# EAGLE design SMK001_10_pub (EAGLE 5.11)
AUTHOR: Nigel Batten; DATE: 16 Apr 2011; PRODUCT: SweeperMeter; RANGE: Other; VERSION: 1.0
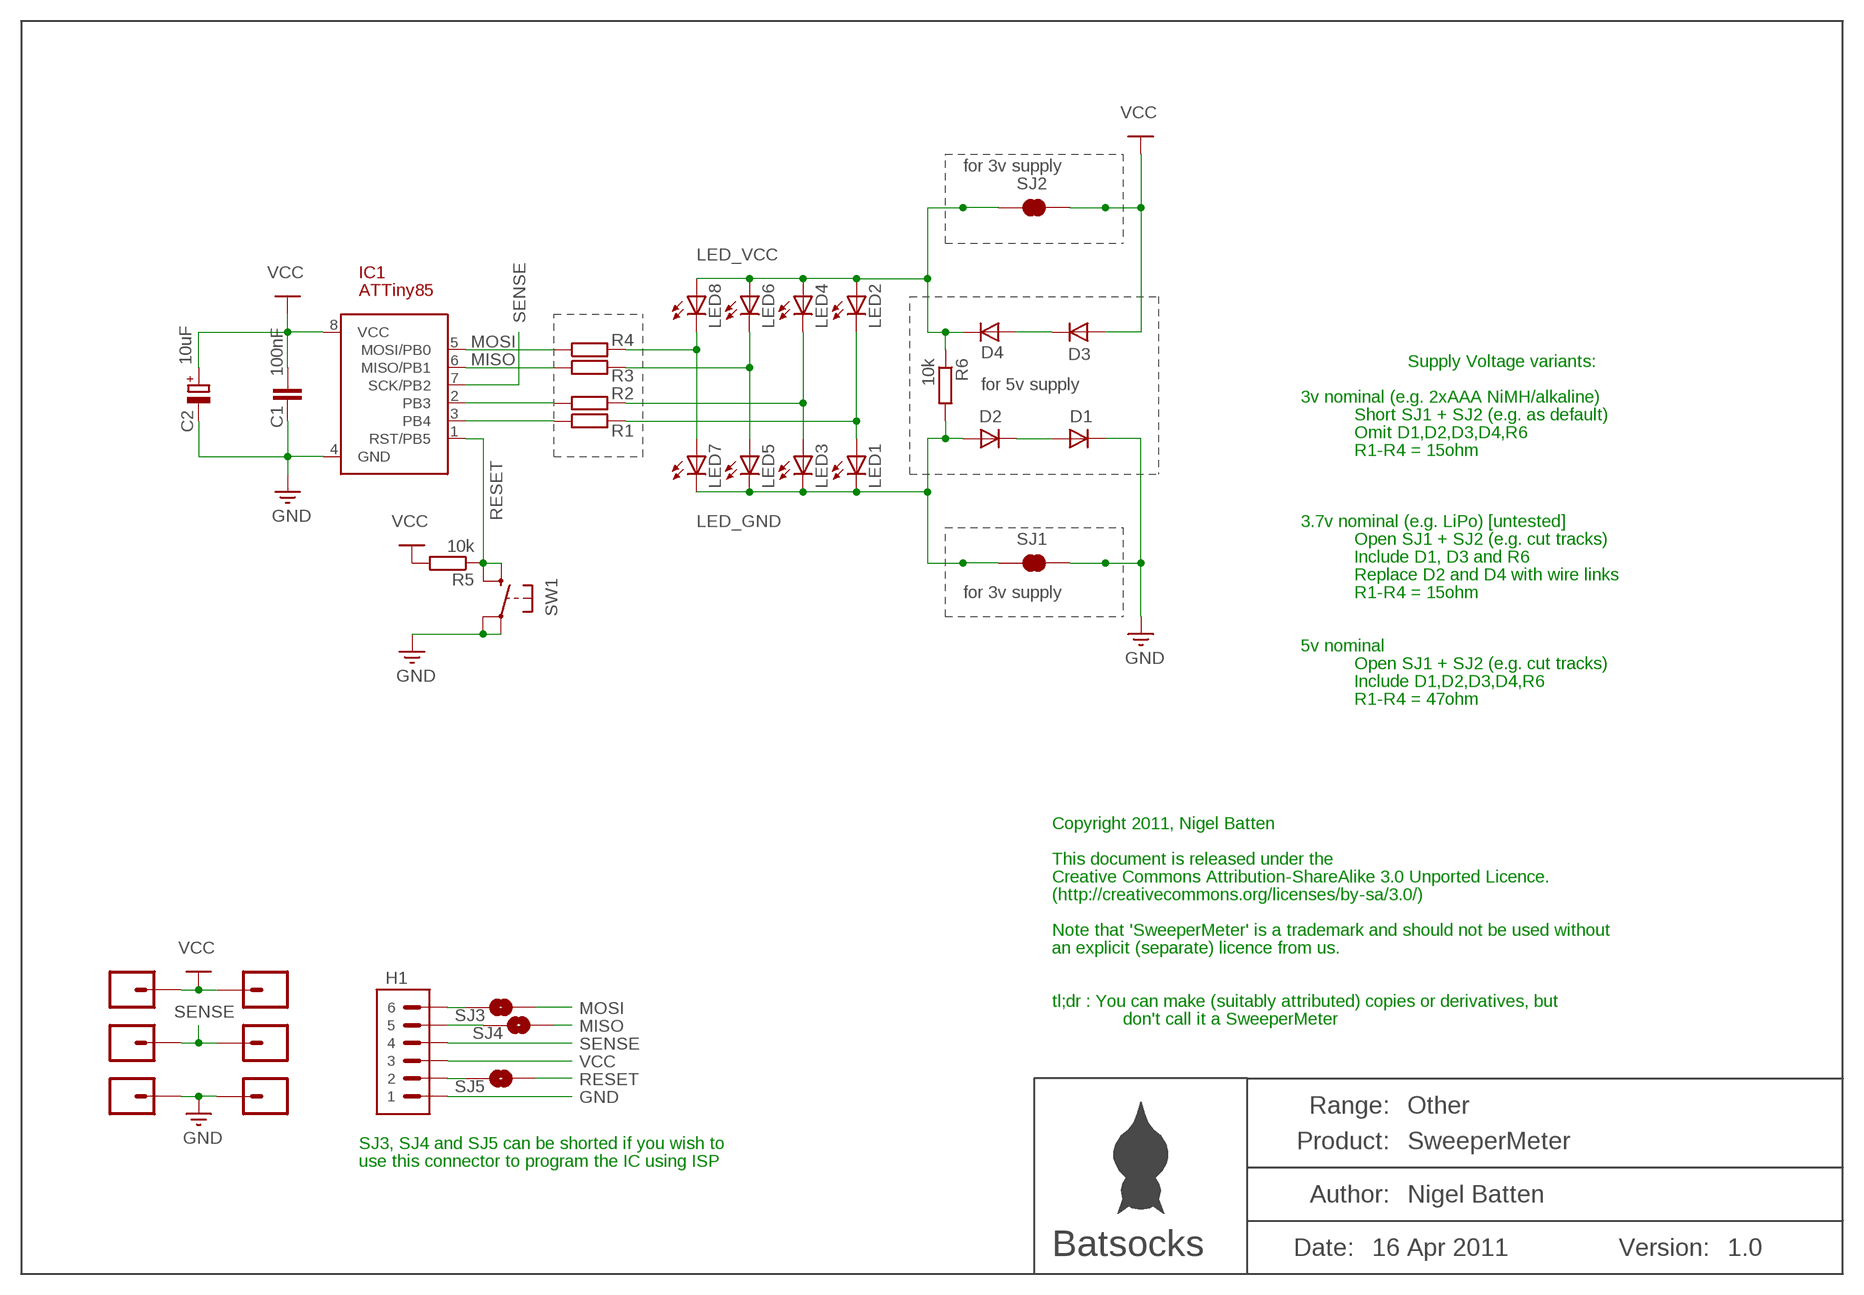
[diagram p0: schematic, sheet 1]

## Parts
C1  100nF  C_EUC050_025X075  [C050_025X075]
C2  10uF  CPOL_EUE15-4  [E15-4]
D1  DIODEDO35_7_OPT  [DO35_7_OPT]
D2  DIODEDO35_7_OPT  [DO35_7_OPT]
D3  DIODEDO35_7_OPT  [DO35_7_OPT]
D4  DIODEDO35_7_OPT  [DO35_7_OPT]
H1  HEADER_6STD  [1X06]
H10  M01FLYING_LEAD  [FLYING_LEAD_PAD]
H11  M01FLYING_LEAD  [FLYING_LEAD_PAD]
H12  M01FLYING_LEAD  [FLYING_LEAD_PAD]
H13  M01FLYING_LEAD  [FLYING_LEAD_PAD]
H14  M01FLYING_LEAD  [FLYING_LEAD_PAD]
H15  M01FLYING_LEAD  [FLYING_LEAD_PAD]
IC1  ATTiny85  ATTINY13V-10PU  [DIL08]
LED1  LED3MM  [LED3MM]
LED2  LED3MM  [LED3MM]
LED3  LED3MM  [LED3MM]
LED4  LED3MM  [LED3MM]
LED5  LED3MM  [LED3MM]
LED6  LED3MM  [LED3MM]
LED7  LED3MM  [LED3MM]
LED8  LED3MM  [LED3MM]
R1  47R  RESISTOR0207/7.5  [R0207/7.5]
R2  47R  RESISTOR0207/7.5  [R0207/7.5]
R3  47R  RESISTOR0207/7.5  [R0207/7.5]
R4  47R  RESISTOR0207/7.5  [R0207/7.5]
R5  10k  RESISTOR0204/5  [R0204/5]
R6  10k  RESISTOR0204/5_OPT  [R0204/5_OPT]
SJ1  SOLDERJUMPER_NC  [SJ_NC]
SJ2  SOLDERJUMPER_NC  [SJ_NC]
SJ3  SOLDERJUMPER_NO  [SJ_NO]
SJ4  SOLDERJUMPER_NO  [SJ_NO]
SJ5  SOLDERJUMPER_NO  [SJ_NO]
SW1  PUSHBUTTON_PTM_4ROUNDPADS  [B3F-10XX-ROUNDPADS]

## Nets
GND [power]: C1.2 C2.- D1.C H1.P$1 H11.P$1 H14.P$1 IC1.4(GND) SJ1.2 SW1.1(P) SW1.2(P1)
LED_GND [LED power]: D2.A LED1.K(C) LED3.K(C) LED5.K(C) LED7.K(C) R6.2 SJ1.1
LED_VCC [LED power]: D4.C LED2.A LED4.A LED6.A LED8.A R6.1 SJ2.1
MISO: IC1.6(MISO/PB1) R3.1 SJ4.1
MOSI: IC1.5(MOSI/PB0) R4.1 SJ3.1
N$1: H1.P$5 SJ4.2
N$3 [LED power]: LED5.A LED6.K(C) R3.2
N$4 [LED power]: LED3.A LED4.K(C) R2.2
N$5 [LED power]: LED1.A LED2.K(C) R1.2
N$6: IC1.3(PB4) R1.1
N$7: D3.C D4.A
N$8: D1.A D2.C
N$9: IC1.2(PB3) R2.1
N$11 [LED power]: LED7.A LED8.K(C) R4.2
N$14: H1.P$2 SJ5.2
N$17: H1.P$6 SJ3.2
RESET: IC1.1(RST/PB5) R5.1 SJ5.1 SW1.3(S) SW1.4(S1)
SENSE: H1.P$4 H12.P$1 H15.P$1 IC1.7(SCK/PB2)
VCC [power]: C1.1 C2.+ D3.A H1.P$3 H10.P$1 H13.P$1 IC1.8(VCC) R5.2 SJ2.2

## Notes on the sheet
- for 3v supply
- Supply Voltage variants:
- for 5v supply
- 3v nominal (e.g. 2xAAA NiMH/alkaline)
- Short SJ1 + SJ2 (e.g. as default)
- Omit D1,D2,D3,D4,R6
- R1-R4 = 15ohm
- 3.7v nominal (e.g. LiPo) [untested]
- Open SJ1 + SJ2 (e.g. cut tracks)
- Include D1, D3 and R6
- Replace D2 and D4 with wire links
- for 3v supply | R1-R4 = 15ohm
- 5v nominal
- Open SJ1 + SJ2 (e.g. cut tracks)
- Include D1,D2,D3,D4,R6
- R1-R4 = 47ohm
- Copyright 2011, Nigel Batten
- This document is released under the
- Creative Commons Attribution-ShareAlike 3.0 Unported Licence.
- (http://creativecommons.org/licenses/by-sa/3.0/)
- Note that 'SweeperMeter' is a trademark and should not be used without
- an explicit (separate) licence from us.
- H1
- tl;dr : You can make (suitably attributed) copies or derivatives, but
- don't call it a SweeperMeter
- SJ3, SJ4 and SJ5 can be shorted if you wish to
- use this connector to program the IC using ISP

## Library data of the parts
C1 = Batten:C_EU
C2 = Batten:CPOL_EU
D1-D4 = Batten:DIODE
H1 = Batten:HEADER_6
H10-H15 = Batten:M01: Header 1
IC1 = Batten:ATTINY13V-10*
LED1-LED8 = Batten:LED: LED
R1-R6 = Batten:RESISTOR
SJ1 SJ2 = Batten:SOLDERJUMPER_NC: Solder Jumper
SJ3-SJ5 = Batten:SOLDERJUMPER_NO: Solder Jumper
SW1 = Batten:PUSHBUTTON_PTM_4: OMRON B3S

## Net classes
0 default: width 0.305 mm, clearance 0.254 mm
1 power: width 0.508 mm, clearance 0.305 mm
2 LED power: width 0.508 mm, clearance 0.305 mm
3 signal: width 0.305 mm, clearance 0.254 mm

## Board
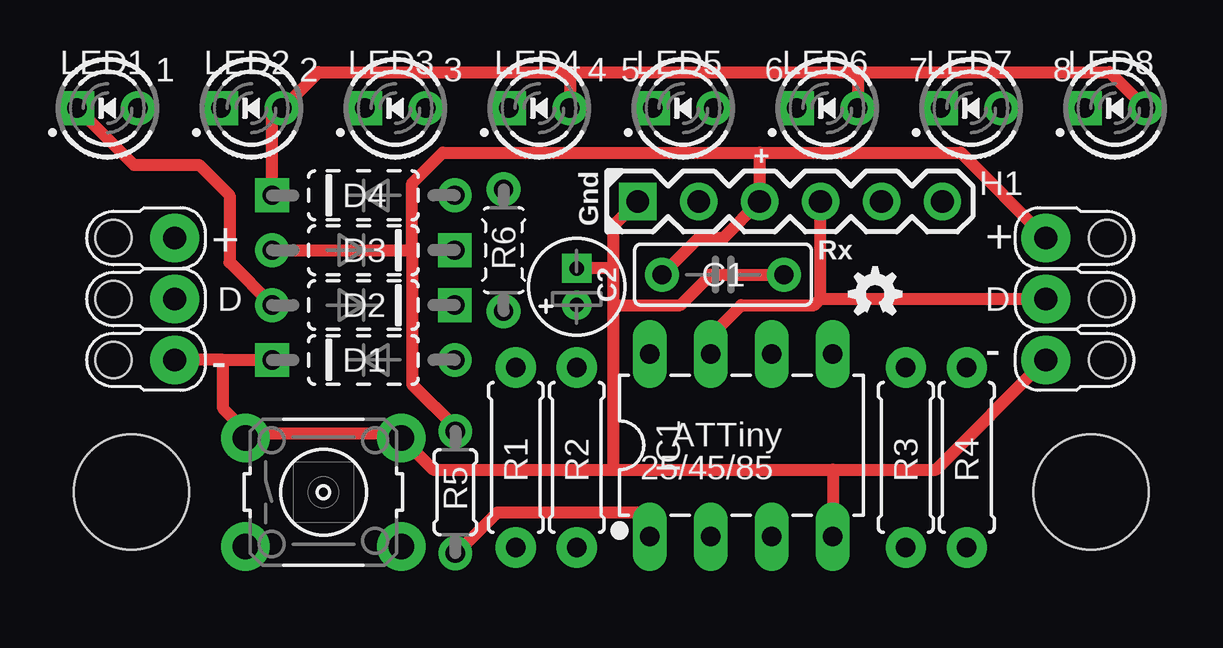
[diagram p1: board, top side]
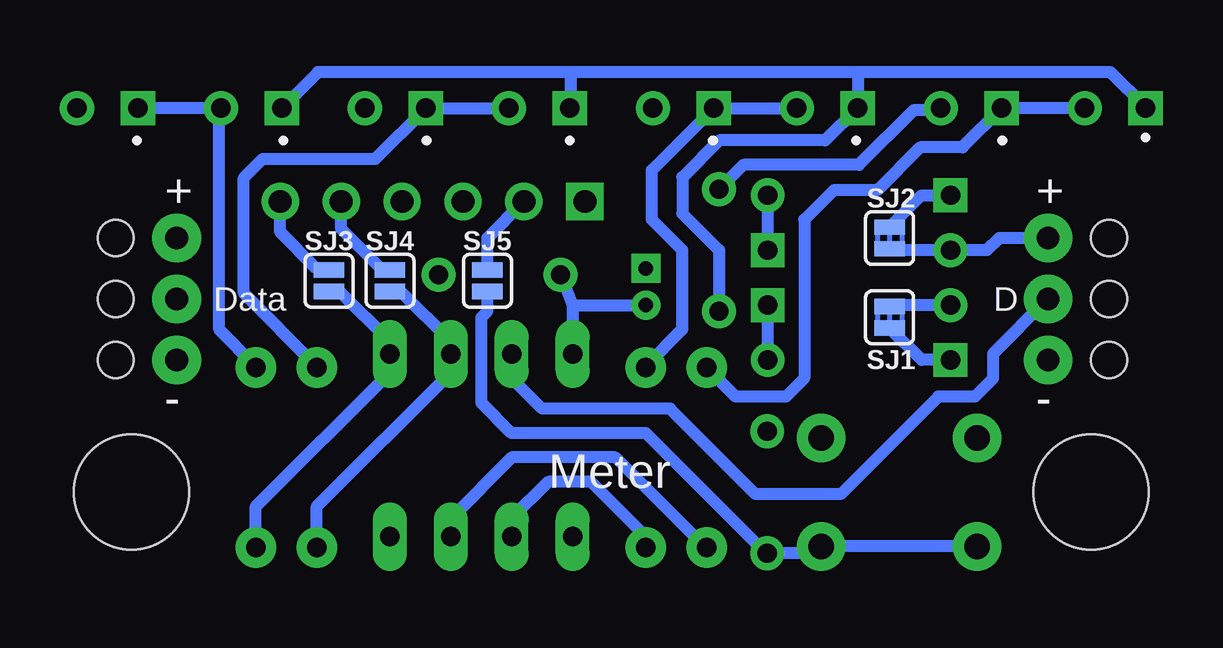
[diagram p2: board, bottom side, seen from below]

No outline drawn. Coordinates in mm, seen from the top.
Copper layers (1*16): Top 0.035mm / dielectric 1.5mm / Bottom 0.035mm
Design rules "Techbridge *": minimum track width 6mil, minimum drill 0.35mm, track to track 12mil, track to pad 12mil, pad to pad 12mil, via to via 12mil, smd to smd 8mil, copper to edge 16mil, drill to drill 8mil, minimum pad ring 12mil, minimum via ring 10mil, stop-mask expansion 4mil, vias tented up to drill 25mil, thermal gap 10mil
Holes 4.8 mm at 17,11 57,11
tKeepout: area 13,7 to 21,15; area 53,7 to 61,15

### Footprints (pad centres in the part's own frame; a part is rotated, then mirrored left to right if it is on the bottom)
C050_025X075 = drill 0.8 round: 1 -2.54,0; 2 2.54,0
E15-4 = drill 0.6 round: + -0.766,0 | drill 0.6 square: - 0.766,0
DO35_7_OPT = drill 0.8 round: A 3.81,0 | drill 0.8 square: C -3.81,0
1X06 = drill 0.95 square: P$1 -6.35,0 | drill 0.95 round: P$2 -3.81,0; P$3 -1.27,0; P$4 1.27,0; P$5 3.81,0; P$6 6.35,0
FLYING_LEAD_PAD = drill 0.95 pad 2.032 round: P$1 0,0 | hole 1.5: -2.54,0
DIL08 = drill 0.813 long: 1 -3.81,-3.81; 2 -1.27,-3.81; 3 1.27,-3.81; 4 3.81,-3.81; 5 3.81,3.81; 6 1.27,3.81; 7 -1.27,3.81; 8 -3.81,3.81
LED3MM = drill 0.813 round: A -1.27,0 | drill 0.813 square: K 1.27,0
R0207/7.5 = drill 0.813 pad 1.676 round: 1 -3.75,0; 2 3.75,0
R0204/5 = drill 0.8 round: 1 -2.54,0; 2 2.54,0
R0204/5_OPT = drill 0.8 round: 1 -2.54,0; 2 2.54,0
SJ_NC = smd 0.635 x 1.27: 1 -0.45,0; 2 0.45,0
SJ_NO = smd 0.635 x 1.27: 1 -0.45,0; 2 0.45,0
B3F-10XX-ROUNDPADS = drill 1.05 pad 2.032 round: 1 -3.251,2.261; 2 3.251,2.261; 3 -3.251,-2.261; 4 3.251,-2.261

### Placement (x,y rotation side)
C1  41.66,20.07 0 top
C2  35.56,19.56 90 top
D1  26.67,16.51 0 top
D2  26.67,18.8 180 top
D3  26.67,21.08 180 top
D4  26.67,23.37 0 top
H1  44.45,23.11 0 top
H10  18.8,21.59 0 top
H11  18.8,16.51 0 top
H12  18.8,19.05 0 top
H13  55.12,21.59 180 top
H14  55.12,16.51 180 top
H15  55.12,19.05 180 top
IC1  42.42,12.95 0 top
LED1  16,27 180 top
LED2  22,27 180 top
LED3  28,27 180 top
LED4  34,27 180 top
LED5  40,27 180 top
LED6  46,27 180 top
LED7  52,27 180 top
LED8  58,27 180 top
R1  33.02,12.45 90 top
R2  35.56,12.45 90 top
R3  49.28,12.45 90 top
R4  51.82,12.45 90 top
R5  30.5,11 90 top
R6  32.51,21.08 270 top
SJ1  25.4,18.29 270 bottom
SJ2  25.4,21.59 270 bottom
SJ3  48.77,19.81 90 bottom
SJ4  46.23,19.81 90 bottom
SJ5  42.16,19.81 90 bottom
SW1  25,11 0 top

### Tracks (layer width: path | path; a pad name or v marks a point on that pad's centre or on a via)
GND
  Top 0.508: 46.23,11.94 50.55,11.94 H14.P$1 | 46.23,11.94 IC1.4 | 21.59,13.46 21.59,13.72 20.83,14.48 20.83,16.51 | 21.59,13.46 28.25,13.46 SW1.2 29.57,11.94 37.08,11.94 | 20.83,16.51 H11.P$1 | 20.83,16.51 D1.C | SW1.1 21.75,13.3 21.59,13.46 | 37.08,11.94 46.23,11.94 | 37.08,11.94 37.08,18.8 | 37.08,18.8 37.08,20.32 | 37.08,20.32 37.08,22.1 H1.P$1 | C2.- 37.08,20.32 | C1.2 41.15,20.07 39.88,18.8 37.08,18.8
  Bottom 0.508: D1.C 24.07,16.51 SJ1.2
LED_GND
  Top 0.508: D2.A 21.08,20.57 21.08,23.37 19.81,24.64 17.09,24.64 LED1.K
  Bottom 0.508: 38.7,28.5 38.7,27 LED5.K | 38.7,28.5 49.23,28.5 LED7.K | 26.7,28.5 38.7,28.5 | 26.7,28.5 26.73,28.47 LED3.K 28.08,25.65 32.51,25.65 34.04,24.13 34.04,22.61 32.51,21.08 R6.2 | 26.7,28.5 16.2,28.5 14.73,27.03 LED1.K | D2.A 25.34,18.8 SJ1.1
LED_VCC
  Top 0.508: LED8.A 57.77,28.5 47.27,28.5 | 35.3,28.5 24.8,28.5 23.3,27 LED2.A 22.86,26.59 D4.C | LED4.A 35.27,28.47 35.3,28.5 | 47.27,28.5 LED6.A | 35.3,28.5 47.27,28.5
  Bottom 0.508: R6.1 31.5,24.64 26.67,24.64 24.38,26.92 23.35,26.92 LED2.A | D4.C 24.07,23.37 SJ2.1
MISO
  Bottom 0.508: R3.1 49.28,10.41 43.69,16 IC1.6 43.69,17.27 45.78,19.36 SJ4.1
MOSI
  Bottom 0.508: R4.1 51.82,10.41 46.23,16 IC1.5 46.23,17.27 48.32,19.36 SJ3.1
N$1
  Bottom 0.508: SJ4.2 46.55,20.26 48.26,21.97 H1.P$5
N$3
  Bottom 0.508: LED5.A LED6.K 46.84,24.89 51.53,24.89 52.32,24.1 52.32,19.3 49.28,16.26 R3.2
N$4
  Bottom 0.508: LED3.A LED4.K 35.31,24.42 35.31,22.35 34.04,21.08 34.04,17.78 35.56,16.26 R2.2
N$5
  Bottom 0.508: LED1.A LED2.K | LED2.K 20.73,26.97 | LED2.K | LED2.K 22.36,25.37 24.13,25.37 25.91,23.59 27.72,23.59 28.96,22.35 28.96,15.75 29.72,14.99 31.81,14.99 R1.2
N$6
  Bottom 0.508: IC1.3 43.69,9.91 41.15,12.45 36.83,12.45 33.08,8.7 R1.1
N$7
  Bottom 0.508: D3.C D4.A
N$8
  Bottom 0.508: D1.A D2.C
N$9
  Bottom 0.508: IC1.2 41.15,9.91 39.62,11.43 37.85,11.43 35.56,9.14 R2.1
N$11
  Bottom 0.508: LED8.K LED7.A 53.34,26.93 53.34,17.78 51.82,16.26 R4.2
N$14
  Bottom 0.508: H1.P$2 42.16,21.59 SJ5.2
N$17
  Bottom 0.508: H1.P$6 50.8,21.84 49.28,20.32 48.83,20.32 SJ3.2
RESET
  Top 0.508: R5.1 30.56,8.46 32.26,10.16 38.61,10.16 IC1.1
  Bottom 0.508: SW1.3 SW1.4 28.53,8.46 R5.1 30.56,8.46 35.56,13.46 41.15,13.46 42.42,14.73 42.42,18.29 42.16,18.54 SJ5.1 42.22,19.3
SENSE
  Top 0.508: IC1.7 41.15,17.53 42.42,18.8 45.47,18.8 45.72,19.05 | 45.72,19.05 H15.P$1 | 45.72,19.05 H1.P$4
  Bottom 0.508: H12.P$1 21.08,16.76 21.08,15.75 21.84,14.99 23.37,14.99 27.43,10.92 30.99,10.92 34.54,14.48 39.88,14.48 41.15,15.75 IC1.7
VCC
  Top 0.508: 43.18,25.15 29.97,25.15 28.7,23.88 28.7,21.08 | 43.18,25.15 51.56,25.15 H13.P$1 | R5.2 30.5,13.7 28.7,15.49 28.7,21.08 | D3.A 28.7,21.08 | C1.1 40.64,21.59 41.66,21.59 H1.P$3 43.18,25.15
  Bottom 0.508: H10.P$1 20.83,21.59 21.34,21.08 D3.A 25.4,21.08 SJ2.2 | C2.+ 38.6,18.79 38.61,18.8 | 38.61,18.8 IC1.8 | C1.1 38.61,18.8

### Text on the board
tPlace: 1 | 2 | 3 | 4 | 5 | 6 | 7 | 8 | + | Gnd | + | Rx | + | D | D | - | -
bPlace: + | + | D | Data | - | - | Meter
tNames: ATTiny | 25/45/85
